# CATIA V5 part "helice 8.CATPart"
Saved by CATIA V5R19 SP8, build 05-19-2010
Part number: helice 8
Bounding box of the stored display mesh (mm): x -17.321 to 17.321, y -30 to 195, z -10 to 20
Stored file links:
  G:\EU_thinkMotion\CFAO_2010\MMS_groupe2\MMS_groupe2\A reprendre\splanchenault\Planchenault\helice 8.CATPart
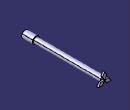
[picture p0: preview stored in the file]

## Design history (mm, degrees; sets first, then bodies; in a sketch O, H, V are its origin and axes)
Body1 (main body)
  Sketch1 on xy-plane, origin (0, 0, 0), H (1, 0, 0), V (0, 1, 0)
    line L1 (0, 0) -> (0, -30)
    line L2 (0, -30) -> (10, -30)
    line L3 (10, -30) -> (10, 0)
    point P3 (10, 0)
    line L4 (10, 0) -> (7.5, 0)
    line L5 (7.5, 0) -> (7.5, 190)
    line L6 (7.5, 190) -> (0, 190)
    line L7 (0, 0) -> (0, 190)
    length L2 = 10
    length L6 = 7.5
    length L7 = 190
    vertical: L1 V, L3 V, L5 V, L7 V
    horizontal: L2 H, L4 H, L6 H
    coincidence: P3 H
  Shaft1: profile Sketch1, axis Sketch1.L7, angle 360
  Sketch2 on face of Shaft1 from Sketch1.L6, origin (0, 190, 0), H (-1, 0, 0), V (0, 0, 1)
    construction line L1 (-27.3861, -15.8114) -> (27.3861, 15.8114)
    axis line L2 (27.3861, -15.8114) -> (-27.3861, 15.8114)
    line L3 (0, 0) -> (5.7735, 10)
    point P5 (5.7735, 10)
    line L4 (5.7735, 10) -> (0, 20)
    point P6 (0, 20)
    line L5 (0, 20) -> (-5.7735, 10)
    point P7 (-5.7735, 10)
    line L6 (-5.7735, 10) -> (0, 0)
    point P8 (-11.547, 0)
    point P9 (-17.3205, -10)
    line L7 (-17.3205, -10) -> (-11.547, 0)
    point P10 (-5.7735, -10)
    line L8 (-5.7735, -10) -> (-17.3205, -10)
    point P11 (0, 0)
    line L9 (-11.547, 0) -> (0, 0)
    line L10 (0, 0) -> (-5.7735, -10)
    point P12 (5.7735, -10)
    point P13 (17.3205, -10)
    line L11 (17.3205, -10) -> (5.7735, -10)
    point P14 (11.547, 0)
    line L12 (11.547, 0) -> (17.3205, -10)
    point P15 (0, 0)
    line L13 (0, 0) -> (11.547, 0)
    line L14 (5.7735, -10) -> (0, 0)
    angle L1 V = 60
    angle L2 V = 60
    coincidence: L1 O, L2 O, P6 V, O P11, O P15, P11 P15
    perpendicularity: L3 L2, L4 L1
    parallelism: L5 L3
    symmetry: P7 P8 L2, P6 P9 L2, L5 L7 L2, P5 P10 L2, L4 L8 L2, O P11 L2, L6 L9 L2, L3 L10 L2, P7 P12 L1, P6 P13 L1, L5 L11 L1, P5 P14 L1, L4 L12 L1, O P15 L1, L3 L13 L1, L6 L14 L1
  Pad1: profile Sketch2, direction (0, 1, 0), length 5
